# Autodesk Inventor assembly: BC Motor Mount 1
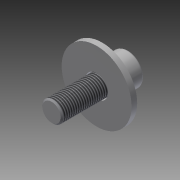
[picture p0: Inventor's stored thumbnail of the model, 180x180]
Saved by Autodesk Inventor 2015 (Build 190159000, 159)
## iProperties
Created: 2007-02
Part Number: BC Motor Mount 1
Document SubType Name: Assembly
Designer: Autodesk, Inc.
Mass: 40.8056 g
Surface Area: 39.4938 cm^2
Volume: 5.19155 cm^3
Density: 7.86 g/cm^3
ClientObjectVersion: 1
Author: Autodesk, Inc.
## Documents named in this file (4)
- C:\Users\Public\Documents\Autodesk\Inventor 2015\Samples\Models\Assemblies\Blower\Blower\Design Accelerator\BC Exhaust 32.iam
- C:\Users\Public\Documents\Autodesk\Inventor 2015\Samples\Standard Parts\en-US\ANSI B18.22.1\ANSI B18.22.1 - 3_8 - wide - Type B.ipt
- C:\Users\Public\Documents\Autodesk\Inventor 2015\Samples\Standard Parts\en-US\ANSI B18.21.1\ANSI B18.21.1 - 0.375.ipt
- C:\Users\Public\Documents\Autodesk\Inventor 2015\Samples\Standard Parts\en-US\ANSI B18.3(13)\ANSI B18.3 - 3_8-24 UNF - 1(22).ipt
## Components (3 placed, 3 different names)
1. ANSI B18.22.1 - 3/8 - wide - Type B:1
2. ANSI B18.21.1 - 0.375:2
3. ANSI B18.3 - 3/8-24 UNF - 1:3
